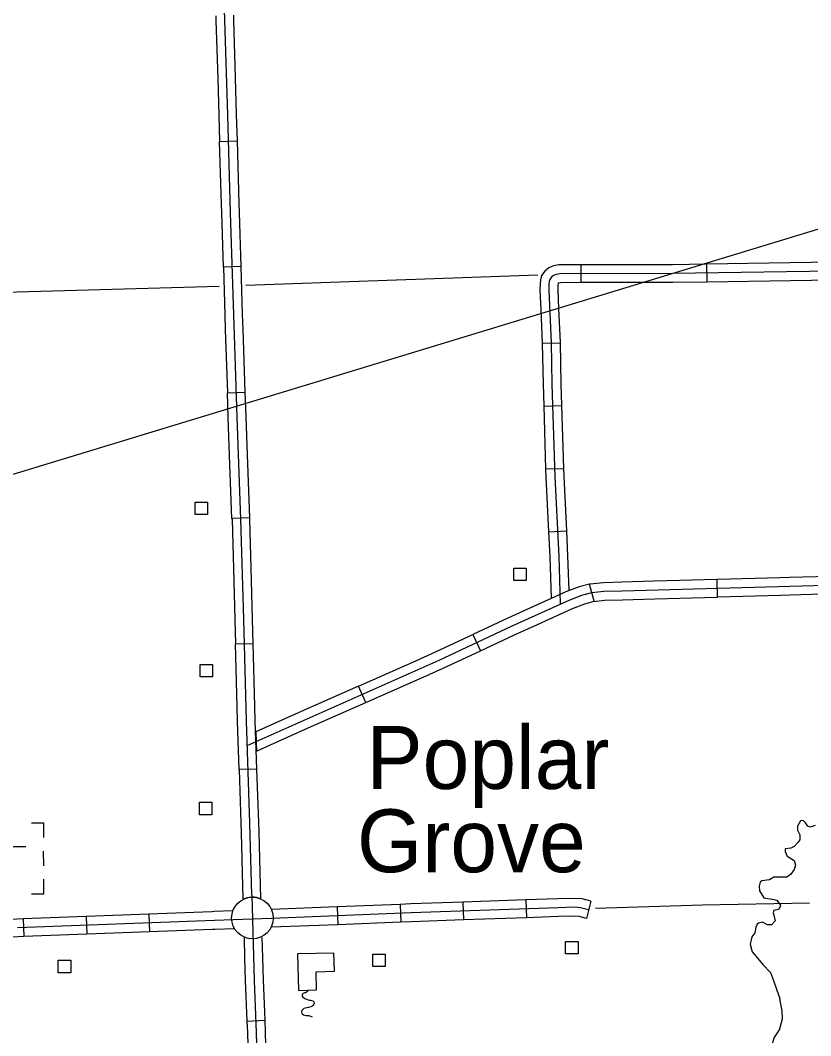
# Model space of a CAD drawing. Extents: x 155 to 3386, y 68 to 2138.
# Drawn here: x 1365.4 to 1555.1, y 551.2 to 794.9 of the extents above; entities that cross this region are included whole.
import ezdxf

# ---------------------------------------------------------------- set-up
doc = ezdxf.new("R2010")
doc.units = 0
for name, color, linetype in [('2', 7, 'Continuous'), ('Level 24', 7, 'Continuous'), ('Level 31', 7, 'Continuous'), ('Level 32', 7, 'Continuous'), ('Level 35', 7, 'Continuous'), ('Level 45', 7, 'Continuous'), ('Level 5', 7, 'Continuous'), ('Level 56', 7, 'Continuous'), ('Level 57', 7, 'Continuous')]:
    doc.layers.add(name, color=color, linetype=linetype)

msp = doc.modelspace()

# ---------------------------------------------------------------- linework, layer by layer
at = {"layer": '2'}
msp.add_line((1715.85, 793.15), (1068.19, 596), dxfattribs=at)
at = {"layer": 'Level 24'}
msp.add_circle((1421.11, 579.48), 5, dxfattribs=at)
at = {"layer": 'Level 31'}
for p, q in [((1413.22, 765.88), (1417.5, 766.01)), ((1418.41, 735.85), (1414.13, 735.72)), ((1415.09, 705.56), (1419.38, 705.7)), ((1420.48, 675.56), (1416.2, 675.4)), ((1532.78, 656.51), (1532.66, 660.79)), ((1503.14, 655.5), (1502.02, 659.64)), ((1503.14, 655.5), (1503.14, 655.5)), ((1474.02, 647.52), (1475.84, 643.64)), ((1417.03, 645.26), (1421.31, 645.37)), ((1448.3, 631.2), (1446.56, 635.12)), ((1422.2, 615.23), (1417.91, 615.09)), ((1422.2, 615.23), (1422.2, 615.23))]:
    msp.add_line(p, q, dxfattribs=at)
for points in [[(1420.96, 585), (1420.5, 602.36), (1419.65, 626.77), (1419.02, 651.18), (1418.35, 675.21), (1417.43, 699.69), (1416.62, 724.28), (1415.88, 748.76), (1415.17, 772.25), (1414.5, 794.97), (1413.66, 819.52), (1412.85, 843.76), (1412.35, 867.99), (1411.58, 891.84), (1410.77, 916.92), (1409.92, 941.23), (1409.21, 964.58), (1408.72, 989.66), (1407.91, 1014.21), (1407.76, 1018.97)], [(1412.32, 796.03), (1412.36, 794.9), (1412.77, 780.96)], [(1417.06, 781.09), (1416.65, 795.04), (1416.61, 796.18)], [(1412.77, 780.96), (1413.03, 772.19), (1413.22, 765.88)], [(1417.5, 766.01), (1417.32, 772.32), (1417.06, 781.09)], [(1413.67, 750.8), (1413.22, 765.88)], [(1417.96, 750.93), (1417.5, 766.01)], [(1414.13, 735.72), (1413.74, 748.69), (1413.67, 750.8)], [(1418.41, 735.85), (1418.02, 748.82), (1417.96, 750.93)], [(1414.13, 735.72), (1414.48, 724.21), (1414.6, 720.64)], [(1418.88, 720.78), (1418.76, 724.34), (1418.41, 735.85)], [(1414.6, 720.64), (1415.09, 705.56)], [(1419.38, 705.7), (1418.88, 720.78)], [(1415.63, 690.47), (1415.29, 699.61), (1415.09, 705.56)], [(1419.91, 690.63), (1419.57, 699.76), (1419.38, 705.7)], [(1416.2, 675.4), (1415.63, 690.47)], [(1420.48, 675.56), (1419.91, 690.63)], [(1416.2, 675.4), (1416.21, 675.14), (1416.62, 660.34)], [(1420.9, 660.46), (1420.49, 675.28), (1420.48, 675.56)], [(1419.85, 620.92), (1432.05, 626.35), (1465.97, 641.38), (1483.32, 649.51), (1497.11, 655.77), (1500.21, 656.93), (1502.6, 657.57), (1505.5, 657.9), (1509.88, 658.02), (1550.12, 659.12), (1607.71, 660.73), (1647.88, 661.64)], [(1421.31, 645.37), (1421.16, 651.24), (1420.9, 660.46)], [(1517.58, 660.38), (1532.66, 660.79)], [(1532.66, 660.79), (1547.74, 661.2)], [(1547.74, 661.2), (1550.06, 661.26), (1562.82, 661.62)], [(1416.62, 660.34), (1416.87, 651.12), (1417.03, 645.26)], [(1502.02, 659.64), (1499.55, 658.97), (1496.3, 657.75), (1487.73, 653.87)], [(1502.02, 659.64), (1502.2, 659.68), (1505.35, 660.03), (1509.82, 660.17), (1517.58, 660.38)], [(1503, 655.46), (1505.65, 655.76), (1509.94, 655.88), (1517.7, 656.09)], [(1517.7, 656.09), (1532.78, 656.51)], [(1547.86, 656.92), (1532.78, 656.51)], [(1562.94, 657.34), (1550.18, 656.98), (1547.86, 656.92)], [(1487.73, 653.87), (1482.42, 651.45), (1474.02, 647.52)], [(1489.5, 649.96), (1497.93, 653.79), (1500.87, 654.89), (1503.14, 655.5)], [(1475.84, 643.64), (1484.21, 647.56), (1489.5, 649.96)], [(1460.35, 641.24), (1465.08, 643.33), (1474.02, 647.52)], [(1417.42, 630.18), (1417.03, 645.26)], [(1421.7, 630.29), (1421.31, 645.37)], [(1462.09, 637.32), (1466.86, 639.43), (1475.84, 643.64)], [(1446.56, 635.12), (1460.35, 641.24)], [(1448.3, 631.2), (1462.09, 637.32)], [(1446.56, 635.12), (1432.77, 629.01)], [(1434.51, 625.09), (1448.3, 631.2)], [(1417.91, 615.09), (1417.51, 626.71), (1417.42, 630.18)], [(1422.2, 615.23), (1421.79, 626.84), (1421.7, 630.29)], [(1432.77, 629.01), (1431.18, 628.31), (1421.89, 624.17), (1422.05, 619.55)], [(1422.05, 619.55), (1432.92, 624.39), (1434.51, 625.09)], [(1417.91, 615.09), (1418.36, 602.29), (1418.42, 600.03)], [(1422.7, 600.14), (1422.64, 602.42), (1422.2, 615.23)], [(1418.42, 600.03), (1418.84, 583.94)], [(1423.12, 584.06), (1422.7, 600.14)]]:
    msp.add_lwpolyline(points, dxfattribs=at)
msp.add_arc((1421.11, 579.48), 5, 66.2768, 117.03, dxfattribs=at)
at = {"layer": 'Level 32'}
for p, q in [((1490.67, 717.45), (1494.95, 717.54)), ((1491.02, 702.35), (1495.3, 702.48)), ((1491.48, 687.27), (1495.76, 687.4)), ((1492.18, 672.16), (1496.46, 672.37)), ((1456.54, 582.76), (1456.71, 578.48)), ((1471.63, 583.3), (1471.78, 579.02)), ((1486.71, 583.83), (1486.86, 579.55)), ((1502.33, 583.55), (1501.27, 579.4)), ((1396.25, 580.42), (1396.41, 576.14)), ((1441.47, 582.17), (1441.64, 577.88)), ((1366.1, 579.3), (1366.26, 575.01)), ((1381.18, 579.86), (1381.34, 575.58)), ((1419.78, 554.76), (1424.06, 554.93))]:
    msp.add_line(p, q, dxfattribs=at)
for points in [[(1490.67, 717.45), (1490.86, 707.58), (1491.02, 702.35)], [(1492.81, 717.49), (1493, 707.63), (1493.68, 685.37), (1494.62, 666.31), (1494.99, 654.8)], [(1494.95, 717.54), (1495.15, 707.68), (1495.3, 702.48)], [(1491.02, 702.35), (1491.48, 687.27)], [(1495.3, 702.48), (1495.76, 687.4)], [(1491.48, 687.27), (1491.54, 685.29), (1492.18, 672.16)], [(1495.76, 687.4), (1495.82, 685.46), (1496.46, 672.37)], [(1492.18, 672.16), (1492.47, 666.22), (1492.8, 656.16)], [(1496.46, 672.37), (1496.76, 666.39), (1497.03, 658.02)], [(1420.96, 585), (1421.53, 564.52), (1422.03, 552.04), (1423.1, 513.6)], [(1456.54, 582.76), (1441.47, 582.17)], [(1471.63, 583.3), (1459.11, 582.86), (1456.54, 582.76)], [(1486.71, 583.83), (1471.63, 583.3)], [(1502.33, 583.55), (1500.24, 584.08), (1498.67, 584.19), (1494.45, 584.1), (1486.71, 583.83)], [(1501.8, 581.47), (1499.9, 581.96), (1498.62, 582.05), (1494.51, 581.96), (1459.19, 580.72), (1425.68, 579.4), (1412.03, 578.87), (1364.7, 577.1)], [(1396.25, 580.42), (1381.18, 579.86)], [(1411.33, 580.98), (1396.25, 580.42)], [(1416.34, 581.18), (1411.95, 581.01), (1411.33, 580.98)], [(1441.47, 582.17), (1425.67, 581.54)], [(1366.1, 579.3), (1364.64, 579.24), (1351.07, 579.05)], [(1381.18, 579.86), (1366.1, 579.3)], [(1441.64, 577.88), (1425.59, 577.25)], [(1456.71, 578.48), (1441.64, 577.88)], [(1471.78, 579.02), (1459.27, 578.58), (1456.71, 578.48)], [(1486.86, 579.55), (1471.78, 579.02)], [(1501.27, 579.4), (1499.56, 579.83), (1498.57, 579.9), (1494.57, 579.82), (1486.86, 579.55)], [(1381.34, 575.58), (1366.26, 575.01)], [(1396.41, 576.14), (1381.34, 575.58)], [(1411.49, 576.7), (1396.41, 576.14)], [(1416.83, 576.91), (1412.11, 576.73), (1411.49, 576.7)], [(1366.26, 575.01), (1364.75, 574.96), (1351.13, 574.76)], [(1419.1, 574.89), (1419.24, 569.86)], [(1423.39, 574.8), (1423.52, 569.98)], [(1419.24, 569.86), (1419.39, 564.45), (1419.78, 554.76)], [(1423.52, 569.98), (1423.67, 564.59), (1424.06, 554.93)], [(1419.78, 554.76), (1419.89, 551.97), (1420.23, 539.71)], [(1424.06, 554.93), (1424.17, 552.12), (1424.51, 539.83)]]:
    msp.add_lwpolyline(points, dxfattribs=at)
at = {"layer": 'Level 35'}
for points in [[(1556.18, 601.65), (1555.02, 601.25), (1554.44, 601.51), (1553.86, 602.32), (1553.28, 602.89), (1552.66, 602.81), (1551.99, 601.56), (1551.99, 600.53), (1552.48, 599.42), (1552.48, 598.22), (1552.04, 597.64), (1551.15, 596.66), (1550.39, 596.26), (1549.01, 596.08), (1549.01, 595.41), (1549.5, 594.35), (1551.19, 593.28), (1551.5, 592.16), (1551.15, 591.14), (1550.39, 589.98), (1549.41, 589.31), (1547.99, 589.27), (1546.25, 589.27), (1545.23, 588.65), (1543.36, 588.42), (1542.96, 588.07), (1542.74, 587.13), (1542.87, 585.97), (1543.89, 584.33), (1546.34, 583.92), (1547.01, 583.75), (1547.85, 582.59), (1547.72, 582.01), (1547.28, 581.56), (1546.25, 581.25), (1546.12, 580.72), (1546.39, 579.87), (1546.61, 578.8), (1545.72, 577.82), (1544.74, 577.87), (1543.58, 578.45), (1542.56, 578.27), (1542.29, 578), (1541.93, 577.29), (1541.71, 575.95), (1540.96, 574.93), (1540.6, 573.19), (1541.04, 571.37), (1543.67, 568.34), (1545.45, 566.38), (1546.21, 564.47), (1547.01, 562.19), (1547.68, 560.19)], [(1554.89, 508.59), (1553.75, 513.35), (1551.62, 517.85), (1550.24, 520.6), (1549.87, 523.11), (1549.87, 524.61), (1550.12, 527.73), (1550.12, 528.23), (1550.12, 529.73), (1549.24, 531.11), (1548.62, 532.49), (1548.24, 533.86), (1548.24, 535.61), (1548.49, 540.49), (1546.74, 542.99), (1545.62, 544.87), (1545.62, 546.87), (1545.74, 548.5), (1546.37, 550.75), (1547.62, 552.62), (1548.37, 555.25), (1548.24, 557.13), (1547.68, 560.19)]]:
    msp.add_lwpolyline(points, dxfattribs=at)
at = {"layer": 'Level 45'}
for p, q in [((1499.95, 736.26), (1499.96, 731.97)), ((1530.09, 736.41), (1530.16, 732.12))]:
    msp.add_line(p, q, dxfattribs=at)
for points in [[(1499.95, 736.26), (1494.68, 736.25), (1493.38, 736.01), (1492.28, 735.54), (1491.29, 734.74), (1490.53, 733.66), (1490.24, 732.67), (1490.16, 731.74), (1490.08, 730.17), (1490.3, 725.53)], [(1515.04, 736.27), (1499.95, 736.26)], [(1530.09, 736.41), (1521.97, 736.28), (1515.04, 736.27)], [(1545.18, 736.63), (1530.09, 736.41)], [(1560.26, 736.86), (1545.18, 736.63)], [(1560.29, 734.72), (1521.99, 734.14), (1494.87, 734.11), (1494, 733.95), (1493.39, 733.69), (1492.87, 733.27), (1492.49, 732.72), (1492.36, 732.27), (1492.29, 731.59), (1492.23, 730.17), (1492.81, 717.49)], [(1499.96, 731.97), (1495.07, 731.96), (1494.62, 731.88), (1494.5, 731.83), (1494.47, 731.8), (1494.43, 731.44), (1494.38, 730.17), (1494.58, 725.73)], [(1515.04, 731.99), (1499.96, 731.97)], [(1530.16, 732.12), (1522.01, 732), (1515.04, 731.99)], [(1545.24, 732.35), (1530.16, 732.12)], [(1560.33, 732.58), (1545.24, 732.35)], [(1490.3, 725.53), (1490.67, 717.4)], [(1494.58, 725.73), (1494.95, 717.59)]]:
    msp.add_lwpolyline(points, dxfattribs=at)
at = {"layer": 'Level 5'}
for points in [[(1419.55, 731.35), (1489.6, 733.84)], [(1341.66, 729.13), (1413.11, 731.14)], [(1503.48, 581.86), (1529.12, 582.68), (1554.8, 583.13)]]:
    msp.add_lwpolyline(points, dxfattribs=at)
at = {"layer": 'Level 56'}
for points in [[(1407.33, 676.29), (1407.33, 679.26), (1410.32, 679.26), (1410.32, 676.29)], [(1483.84, 660.47), (1483.84, 663.45), (1486.83, 663.45), (1486.83, 660.47)], [(1408.52, 637.35), (1408.52, 640.32), (1411.5, 640.32), (1411.5, 637.35)], [(1408.42, 604.27), (1408.42, 607.25), (1411.4, 607.25), (1411.4, 604.27)], [(1496.29, 570.91), (1496.29, 573.88), (1499.27, 573.88), (1499.27, 570.91)], [(1450.02, 567.84), (1450.02, 570.81), (1453, 570.81), (1453, 567.84)], [(1374.5, 566.35), (1374.5, 569.33), (1377.49, 569.33), (1377.49, 566.35)]]:
    msp.add_lwpolyline(points, close=True, dxfattribs=at)
at = {"layer": 'Level 57'}
for p, q in [((1360.96, 596.65), (1366.7, 596.65)), ((1370.96, 593.79), (1370.96, 595.55)), ((1370.96, 593.79), (1370.96, 591.98))]:
    msp.add_line(p, q, dxfattribs=at)
for points in [[(1368.1, 602.36), (1370.96, 602.36), (1370.96, 598.79)], [(1370.96, 588.79), (1370.96, 585.22), (1368.1, 585.22)], [(1434.47, 562.14), (1434.44, 562.07), (1434.42, 562.01), (1434.36, 561.93), (1434.31, 561.87), (1434.27, 561.83), (1434.21, 561.78), (1434.16, 561.74), (1434.1, 561.7), (1433.97, 561.63), (1433.87, 561.59), (1433.77, 561.55), (1433.6, 561.51), (1433.44, 561.44), (1433.25, 561.33), (1433.13, 561.19), (1433.06, 561.01), (1433.05, 560.81), (1433.14, 560.6), (1433.33, 560.37), (1433.7, 560.13), (1434.06, 559.98), (1434.51, 559.85), (1434.83, 559.79), (1435.06, 559.76), (1435.32, 559.72), (1435.64, 559.57), (1435.85, 559.35), (1435.9, 559.07), (1435.83, 558.8), (1435.66, 558.57), (1435.41, 558.34), (1435.1, 558.2), (1434.59, 558.04), (1434.16, 557.93), (1433.76, 557.84), (1433.48, 557.76), (1433.2, 557.56), (1432.97, 557.25), (1432.91, 556.95), (1432.93, 556.67), (1433.02, 556.45), (1433.38, 556.21), (1433.89, 556.09), (1434.22, 556.09), (1434.55, 556.06), (1435.06, 555.93), (1435.45, 555.77)]]:
    msp.add_lwpolyline(points, dxfattribs=at)
msp.add_lwpolyline([(1440.67, 571.06), (1431.93, 570.85), (1432.14, 562.11), (1436.51, 562.21), (1436.41, 566.58), (1440.78, 566.69)], close=True, dxfattribs=at)

# ---------------------------------------------------------------- texts
at = {"layer": 'Level 24'}
for s, p in [('Poplar', (1448.5, 610.46)), ('Grove', (1446.2, 590.47))]:
    msp.add_text(s, height=15.086, dxfattribs=at).set_placement(p)

doc.saveas('drawing.dxf')
